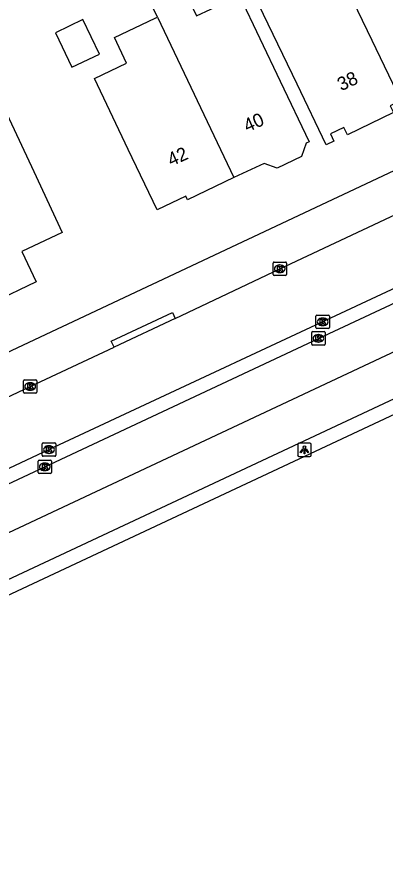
# Model space of a CAD drawing. Extents: x 159280 to 160375, y 384531 to 385872.
# Drawn here: x 160142 to 160169.4, y 384628.5 to 384691.2 of the extents above; entities that cross this region are included whole.
import ezdxf

# ---------------------------------------------------------------- set-up
doc = ezdxf.new("R2010")
doc.units = 0
for name, color, linetype in [('IMGEO_Kolk', 7, 'Continuous'), ('IMGEO_Lichtpunt', 7, 'Continuous'), ('IMGEO_Pand', 7, 'Continuous'), ('IMGEO_Pand_nummerreeks', 7, 'Continuous'), ('IMGEO_Rijbaan_lokaal_open', 7, 'Continuous'), ('IMGEO_Rijbaan_regionaal_gesloten', 7, 'Continuous'), ('IMGEO_Voetpad_open', 7, 'Continuous')]:
    doc.layers.add(name, color=color, linetype=linetype)

msp = doc.modelspace()

# ---------------------------------------------------------------- linework, layer by layer
at = {"layer": 'IMGEO_Kolk'}
for p, q in [((160161.069, 384672.042), (160161.069, 384672.894)), ((160161.144, 384672.968), (160161.996, 384672.968)), ((160162.07, 384672.894), (160162.07, 384672.042)), ((160161.58, 384672.188), (160161.555, 384672.188)), ((160161.557, 384672.748), (160161.582, 384672.748)), ((160161.996, 384671.968), (160161.144, 384671.968)), ((160164.341, 384669.011), (160165.193, 384669.011)), ((160164.266, 384668.085), (160164.266, 384668.937)), ((160164.754, 384668.791), (160164.779, 384668.791)), ((160165.267, 384668.937), (160165.267, 384668.085)), ((160164.021, 384667.78), (160164.873, 384667.78)), ((160165.193, 384668.011), (160164.341, 384668.011)), ((160164.777, 384668.231), (160164.752, 384668.231)), ((160163.946, 384666.854), (160163.946, 384667.706)), ((160164.434, 384667.56), (160164.459, 384667.56)), ((160164.947, 384667.706), (160164.947, 384666.854)), ((160164.873, 384666.78), (160164.021, 384666.78)), ((160164.457, 384667), (160164.432, 384667)), ((160142.472, 384663.264), (160142.472, 384664.116)), ((160142.547, 384664.19), (160143.399, 384664.19)), ((160143.473, 384664.116), (160143.473, 384663.264)), ((160142.983, 384663.41), (160142.958, 384663.41)), ((160142.96, 384663.97), (160142.985, 384663.97)), ((160143.399, 384663.19), (160142.547, 384663.19)), ((160143.877, 384658.563), (160143.877, 384659.415)), ((160143.952, 384659.489), (160144.804, 384659.489)), ((160144.365, 384659.269), (160144.39, 384659.269)), ((160144.878, 384659.415), (160144.878, 384658.563)), ((160144.804, 384658.489), (160143.952, 384658.489)), ((160144.388, 384658.709), (160144.363, 384658.709)), ((160143.562, 384657.283), (160143.562, 384658.135)), ((160143.637, 384658.209), (160144.489, 384658.209)), ((160144.05, 384657.989), (160144.075, 384657.989)), ((160144.563, 384658.135), (160144.563, 384657.283)), ((160144.489, 384657.209), (160143.637, 384657.209)), ((160144.073, 384657.429), (160144.048, 384657.429))]:
    msp.add_line(p, q, dxfattribs=at)
for points in [[(160161.069, 384672.042), (160161.069, 384672.894)], [(160161.144, 384672.968), (160161.996, 384672.968)], [(160162.07, 384672.894), (160162.07, 384672.042)], [(160161.39, 384672.668), (160161.513, 384672.668), (160161.513, 384672.517), (160161.643, 384672.668), (160161.807, 384672.668), (160161.661, 384672.517), (160161.814, 384672.268), (160161.662, 384672.268), (160161.577, 384672.432), (160161.513, 384672.365), (160161.513, 384672.268), (160161.39, 384672.268), (160161.39, 384672.668)], [(160161.996, 384671.968), (160161.144, 384671.968)], [(160164.341, 384669.011), (160165.193, 384669.011)], [(160164.266, 384668.085), (160164.266, 384668.937)], [(160164.587, 384668.711), (160164.71, 384668.711), (160164.71, 384668.56), (160164.84, 384668.711), (160165.004, 384668.711), (160164.858, 384668.56), (160165.011, 384668.311), (160164.859, 384668.311), (160164.774, 384668.475), (160164.71, 384668.408), (160164.71, 384668.311), (160164.587, 384668.311), (160164.587, 384668.711)], [(160165.267, 384668.937), (160165.267, 384668.085)], [(160164.021, 384667.78), (160164.873, 384667.78)], [(160165.193, 384668.011), (160164.341, 384668.011)], [(160163.946, 384666.854), (160163.946, 384667.706)], [(160164.267, 384667.48), (160164.39, 384667.48), (160164.39, 384667.329), (160164.52, 384667.48), (160164.684, 384667.48), (160164.538, 384667.329), (160164.691, 384667.08), (160164.539, 384667.08), (160164.454, 384667.244), (160164.39, 384667.177), (160164.39, 384667.08), (160164.267, 384667.08), (160164.267, 384667.48)], [(160164.947, 384667.706), (160164.947, 384666.854)], [(160164.873, 384666.78), (160164.021, 384666.78)], [(160142.472, 384663.264), (160142.472, 384664.116)], [(160142.547, 384664.19), (160143.399, 384664.19)], [(160143.473, 384664.116), (160143.473, 384663.264)], [(160142.793, 384663.89), (160142.916, 384663.89), (160142.916, 384663.739), (160143.046, 384663.89), (160143.21, 384663.89), (160143.064, 384663.739), (160143.217, 384663.49), (160143.065, 384663.49), (160142.98, 384663.654), (160142.916, 384663.587), (160142.916, 384663.49), (160142.793, 384663.49), (160142.793, 384663.89)], [(160143.399, 384663.19), (160142.547, 384663.19)], [(160143.877, 384658.563), (160143.877, 384659.415)], [(160143.952, 384659.489), (160144.804, 384659.489)], [(160144.198, 384659.189), (160144.321, 384659.189), (160144.321, 384659.038), (160144.451, 384659.189), (160144.615, 384659.189), (160144.469, 384659.038), (160144.622, 384658.789), (160144.47, 384658.789), (160144.385, 384658.953), (160144.321, 384658.886), (160144.321, 384658.789), (160144.198, 384658.789), (160144.198, 384659.189)], [(160144.878, 384659.415), (160144.878, 384658.563)], [(160144.804, 384658.489), (160143.952, 384658.489)], [(160143.562, 384657.283), (160143.562, 384658.135)], [(160143.637, 384658.209), (160144.489, 384658.209)], [(160143.883, 384657.909), (160144.006, 384657.909), (160144.006, 384657.758), (160144.136, 384657.909), (160144.3, 384657.909), (160144.154, 384657.758), (160144.307, 384657.509), (160144.155, 384657.509), (160144.07, 384657.673), (160144.006, 384657.606), (160144.006, 384657.509), (160143.883, 384657.509), (160143.883, 384657.909)], [(160144.563, 384658.135), (160144.563, 384657.283)], [(160144.489, 384657.209), (160143.637, 384657.209)]]:
    msp.add_lwpolyline(points, dxfattribs=at)
for centre, start, end in [((160161.146, 384672.892), 91.55205, 178.44795), ((160161.146, 384672.892), 91.55205, 178.44795), ((160161.994, 384672.892), 1.55205, 88.44795), ((160161.994, 384672.892), 1.55205, 88.44795), ((160161.146, 384672.044), 181.55205, 268.44795), ((160161.146, 384672.044), 181.55205, 268.44795), ((160161.994, 384672.044), 271.55205, 358.44795), ((160161.994, 384672.044), 271.55205, 358.44795), ((160164.343, 384668.935), 91.55205, 178.44795), ((160164.343, 384668.935), 91.55205, 178.44795), ((160165.191, 384668.935), 1.55205, 88.44795), ((160165.191, 384668.935), 1.55205, 88.44795), ((160164.023, 384667.704), 91.55205, 178.44795), ((160164.023, 384667.704), 91.55205, 178.44795), ((160164.343, 384668.087), 181.55205, 268.44795), ((160164.343, 384668.087), 181.55205, 268.44795), ((160164.871, 384667.704), 1.55205, 88.44795), ((160164.871, 384667.704), 1.55205, 88.44795), ((160165.191, 384668.087), 271.55205, 358.44795), ((160165.191, 384668.087), 271.55205, 358.44795), ((160164.023, 384666.856), 181.55205, 268.44795), ((160164.023, 384666.856), 181.55205, 268.44795), ((160164.871, 384666.856), 271.55205, 358.44795), ((160164.871, 384666.856), 271.55205, 358.44795), ((160142.549, 384664.114), 91.55205, 178.44795), ((160142.549, 384664.114), 91.55205, 178.44795), ((160143.397, 384664.114), 1.55205, 88.44795), ((160143.397, 384664.114), 1.55205, 88.44795), ((160142.549, 384663.266), 181.55205, 268.44795), ((160142.549, 384663.266), 181.55205, 268.44795), ((160143.397, 384663.266), 271.55205, 358.44795), ((160143.397, 384663.266), 271.55205, 358.44795), ((160143.954, 384659.413), 91.55205, 178.44795), ((160143.954, 384659.413), 91.55205, 178.44795), ((160144.802, 384659.413), 1.55205, 88.44795), ((160144.802, 384659.413), 1.55205, 88.44795), ((160143.954, 384658.565), 181.55205, 268.44795), ((160143.954, 384658.565), 181.55205, 268.44795), ((160144.802, 384658.565), 271.55205, 358.44795), ((160144.802, 384658.565), 271.55205, 358.44795), ((160143.639, 384658.133), 91.55205, 178.44795), ((160143.639, 384658.133), 91.55205, 178.44795), ((160144.487, 384658.133), 1.55205, 88.44795), ((160144.487, 384658.133), 1.55205, 88.44795), ((160143.639, 384657.285), 181.55205, 268.44795), ((160143.639, 384657.285), 181.55205, 268.44795), ((160144.487, 384657.285), 271.55205, 358.44795), ((160144.487, 384657.285), 271.55205, 358.44795)]:
    msp.add_arc(centre, 0.0765, start, end, dxfattribs=at)
for centre, major_axis, ratio, start_param, end_param in [((160161.556, 384672.468), (-0.387, 0.002), 0.722429, 4.712389, 7.853982), ((160161.581, 384672.468), (-0.39, 0.002), 0.717154, 1.570796, 4.712389), ((160164.753, 384668.511), (-0.387, 0.002), 0.722429, 4.712389, 7.853982), ((160164.778, 384668.511), (-0.39, 0.002), 0.717154, 1.570796, 4.712389), ((160164.433, 384667.28), (-0.387, 0.002), 0.722429, 4.712389, 7.853982), ((160164.458, 384667.28), (-0.39, 0.002), 0.717154, 1.570796, 4.712389), ((160142.959, 384663.69), (-0.387, 0.002), 0.722429, 4.712389, 7.853982), ((160142.984, 384663.69), (-0.39, 0.002), 0.717154, 1.570796, 4.712389), ((160144.364, 384658.989), (-0.387, 0.002), 0.722429, 4.712389, 7.853982), ((160144.389, 384658.989), (-0.39, 0.002), 0.717154, 1.570796, 4.712389), ((160144.049, 384657.709), (-0.387, 0.002), 0.722429, 4.712389, 7.853982), ((160144.074, 384657.709), (-0.39, 0.002), 0.717154, 1.570796, 4.712389)]:
    msp.add_ellipse(centre, major_axis=major_axis, ratio=ratio, start_param=start_param, end_param=end_param, dxfattribs=at)
at = {"layer": 'IMGEO_Lichtpunt'}
for p, q in [((160162.902, 384659.378), (160162.902, 384658.571)), ((160162.902, 384659.378), (160162.902, 384658.571)), ((160163.804, 384659.473), (160162.996, 384659.473)), ((160163.804, 384659.473), (160162.996, 384659.473)), ((160163.898, 384658.571), (160163.898, 384659.378)), ((160163.898, 384658.571), (160163.898, 384659.378)), ((160162.996, 384658.477), (160163.804, 384658.477)), ((160162.996, 384658.477), (160163.804, 384658.477))]:
    msp.add_line(p, q, dxfattribs=at)
for points in [[(160163.276, 384659.042), (160163.315, 384659.014), (160163.127, 384658.752), (160163.089, 384658.779), (160163.276, 384659.042)], [(160163.378, 384658.994), (160163.425, 384658.994), (160163.425, 384658.672), (160163.378, 384658.672), (160163.378, 384658.994)], [(160163.488, 384659.014), (160163.526, 384659.041), (160163.713, 384658.779), (160163.674, 384658.751), (160163.488, 384659.014)]]:
    msp.add_lwpolyline(points, dxfattribs=at)
msp.add_circle((160163.401, 384659.176), 0.0994, dxfattribs=at)
for centre, start, end in [((160162.996, 384659.378), 90, 180), ((160162.996, 384659.378), 90, 180), ((160163.804, 384659.378), 0, 90), ((160163.804, 384659.378), 0, 90), ((160162.996, 384658.571), 180, 270), ((160162.996, 384658.571), 180, 270), ((160163.804, 384658.571), 270, 0), ((160163.804, 384658.571), 270, 360)]:
    msp.add_arc(centre, 0.0946, start, end, dxfattribs=at)
at = {"layer": 'IMGEO_Pand'}
for points in [[(160161.747, 384695.79), (160163.323, 384692.519), (160166.284, 384693.946), (160168.425, 384689.503), (160170.595, 384684.998), (160169.802, 384684.616), (160170.049, 384684.103), (160166.603, 384682.443), (160166.333, 384683.004), (160165.336, 384682.524), (160165.596, 384681.985), (160165.031, 384681.713), (160162.861, 384686.218), (160158.908, 384694.422), (160161.747, 384695.79)], [(160152.461, 384691.218), (160151.724, 384692.765), (160154.116, 384693.904), (160155.353, 384691.307), (160158.563, 384692.835), (160161.609, 384686.441), (160163.759, 384681.926), (160163.529, 384681.817), (160163.182, 384680.839), (160161.37, 384679.976), (160160.395, 384680.322), (160158.157, 384679.256)], [(160144.866, 384690.06), (160146.088, 384687.493), (160148.13, 384688.466), (160146.907, 384691.032), (160144.866, 384690.06)], [(160158.157, 384679.256), (160154.693, 384677.607), (160154.569, 384677.867), (160152.432, 384676.849), (160150.282, 384681.364), (160147.761, 384686.655), (160150.155, 384687.795), (160149.253, 384689.69), (160152.294, 384691.138), (160152.461, 384691.218)], [(160152.461, 384691.218), (160158.157, 384679.256)], [(160136.429, 384677.935), (160141.272, 384680.209), (160140.379, 384682.111), (160139.219, 384681.566), (160137.886, 384684.403), (160140.462, 384685.613), (160143.238, 384679.703), (160145.363, 384675.177), (160142.345, 384673.759), (160143.415, 384671.48), (160140.184, 384669.963)]]:
    msp.add_lwpolyline(points, dxfattribs=at)
at = {"layer": 'IMGEO_Rijbaan_lokaal_open'}
for points in [[(160153.783, 384668.766), (160161.57, 384672.467), (160173.946, 384678.277)], [(160180.653, 384675.929), (160171.723, 384671.759), (160144.378, 384658.99), (160126.055, 384650.383), (160088.841, 384632.92), (160077.69, 384627.699), (160073.801, 384626.037), (160056.041, 384619.086), (160049.251, 384616.444)], [(160153.783, 384668.766), (160149.23, 384666.624)], [(160069.809, 384629.293), (160070.464, 384629.449), (160072.242, 384630.277), (160087.2, 384637.356), (160142.974, 384663.69), (160149.23, 384666.624)]]:
    msp.add_lwpolyline(points, dxfattribs=at)
at = {"layer": 'IMGEO_Rijbaan_regionaal_gesloten'}
for points in [[(160006.675, 384596.052), (160012.896, 384598.112), (160030.199, 384604.442), (160051.41, 384612.075), (160070.258, 384619.89), (160105.075, 384635.724), (160136.86, 384650.709), (160173.534, 384667.91), (160180.357, 384670.981), (160187.384, 384674.159), (160193.16, 384677.338), (160199.61, 384681.383), (160210.295, 384687.933), (160217.514, 384692.075), (160225.023, 384696.313), (160232.339, 384700.069), (160235.287, 384701.39)], [(160046.751, 384614.401), (160055.375, 384617.743), (160075.411, 384625.619), (160077.964, 384626.718), (160090.922, 384632.804), (160109.527, 384641.533), (160128.143, 384650.259), (160144.064, 384657.707), (160164.447, 384667.279), (160172.142, 384670.868), (160181.729, 384675.34), (160189.117, 384679.082), (160200.497, 384685.824), (160200.698, 384685.93)], [(160091.401, 384625.897), (160174.891, 384665.025), (160186.506, 384670.468)], [(160186.974, 384669.525), (160175.34, 384664.07), (160111.783, 384634.269), (160102.714, 384629.928), (160091.931, 384624.72)]]:
    msp.add_lwpolyline(points, dxfattribs=at)
at = {"layer": 'IMGEO_Voetpad_open'}
for points in [[(160186.425, 384687.476), (160110.972, 384651.965)], [(160149.23, 384666.624), (160149.018, 384667.076), (160153.571, 384669.218), (160153.783, 384668.766)]]:
    msp.add_lwpolyline(points, dxfattribs=at)

# ---------------------------------------------------------------- texts
at = {"layer": 'IMGEO_Pand_nummerreeks'}
for s, rotation, p in [('38', 25.19378, (160166.148, 384685.691)), ('40', 24.14444, (160159.145, 384682.619)), ('42', 24.14444, (160153.477, 384680.079))]:
    msp.add_text(s, height=1, rotation=rotation, dxfattribs=at).set_placement(p)

doc.saveas('drawing.dxf')
